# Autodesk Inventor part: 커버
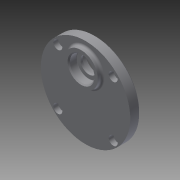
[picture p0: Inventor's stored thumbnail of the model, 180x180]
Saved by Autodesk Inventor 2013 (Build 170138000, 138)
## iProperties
Created: 2015-07
Part Number: 커버
Material: 일반
Document SubType Name: Modeling
Designer: user
Density: 1 g/cm^3
Author: user
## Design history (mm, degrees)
sketch "스케치1"
  geometry: C1 r 40 at (0, 0); 1 further point
  constraints: 1 centre point, 1 coincident
  dimensions: "d0" = 80 diameter of C1
extrude "돌출1" new body sketch "스케치1" distance "d1" = 9; taper "d2" = 0 deg
sketch "스케치2"
  geometry: L1 (0, 0)-(0, 11); L2 (0, 0)-(0, -20); C1 r 40 at (0, 0) reference; C2 r 14 at (0, 11); C3 r 14 at (0, -20)
  constraints: 4 end point, 2 centre point, 2 coincident, 1 collinear, 1 vertical
  dimensions: "d3" = 11 distance of L1.start L1.end; "d4" = 20 distance of L1.start L2.end; "d5" = 28 diameter of C2; "d6" = 28 diameter of C3
extrude "돌출2" join sketch "스케치2" distance "d7" = 3; taper "d8" = 0 deg
sketch "스케치3"
  geometry: C1 r 14 at (0, 0) reference; C2 r 14 at (0, -31) reference; C3 r 11 at (0, 0); C4 r 11 at (0, -31); 1 further point
  constraints: 2 centre point, 2 coincident
  dimensions: "d9" = 22 diameter of C3; "d10" = 22 diameter of C4
extrude "돌출3" cut sketch "스케치3" distance "d11" = 7; taper "d12" = 0 deg
sketch "스케치4"
  geometry: C1 r 9 at (0, 0); 2 further points
  constraints: 1 centre point, 1 coincident, 1 vertical alignment
  dimensions: "d13" = 18 diameter of C1
extrude "돌출4" cut sketch "스케치4" distance "d14" = 1; taper "d15" = 0 deg
sketch "스케치5"
  geometry: C1 r 11 at (0, 0) reference; C2 r 7.5 at (0, 0); 1 further point
  constraints: 1 centre point, 1 coincident
  dimensions: "d16" = 15 diameter of C2
extrude "돌출5" cut sketch "스케치5" distance "d17" = 2; taper "d18" = 0 deg
sketch "스케치6"
  geometry: C1 r 7.5 at (0, 0) reference; C2 r 11 at (0, 0); 1 further point
  constraints: 1 centre point, 1 coincident
  dimensions: "d19" = 22 diameter of C2
extrude "돌출6" cut sketch "스케치6" distance "d20" = 10; taper "d21" = 0 deg
sketch "스케치7"
  geometry: C1 r 11 at (0, 20) reference; C2 r 15 at (0, 20)
  constraints: 1 centre point, 1 coincident
  dimensions: "d22" = 30 diameter of C2
extrude "돌출7" join sketch "스케치7" distance "d23" = 4; taper "d24" = 0 deg
sketch "스케치8"
  geometry: L1 (0, 0)-(35, 0); L2 (0, 0)-(24.749, 24.749); C1 r 40 at (0, 0) reference; A1 r 35 centre (0, 0) between (35, 0) and (24.749, 24.749)
  constraints: 4 end point, 2 point on circle, 1 centre point, 1 coincident, 1 horizontal
  dimensions: "d25" = 70 diameter of A1; "d26" = 45 deg angle of L1 L2
hole "구멍1" sketch "스케치8" at (24.749, 24.749) diameter "d28" = 4.5; stored, may be unused: countersink angle "d32" = 90 deg, drill point angle "d34" = 118 deg; dims "d29" = 6, "d30" = 8, "d31" = 4.4, "d33" = 20
chamfer "모따기1" distance "d38" = 1; stored, may be unused: second distance "d39" = 2, angle "d40" = 45 deg
fillet "모깎기1" dims "d41" = 2
fillet "모깎기2" dims "d42" = 2
fillet "모깎기3" dims "d43" = 0.3
fillet "모깎기4" dims "d44" = 1
node "솔리드1"
pattern_circular "원형 패턴1" dims angle "d36" = 360 deg
node "투영된 루프1"
